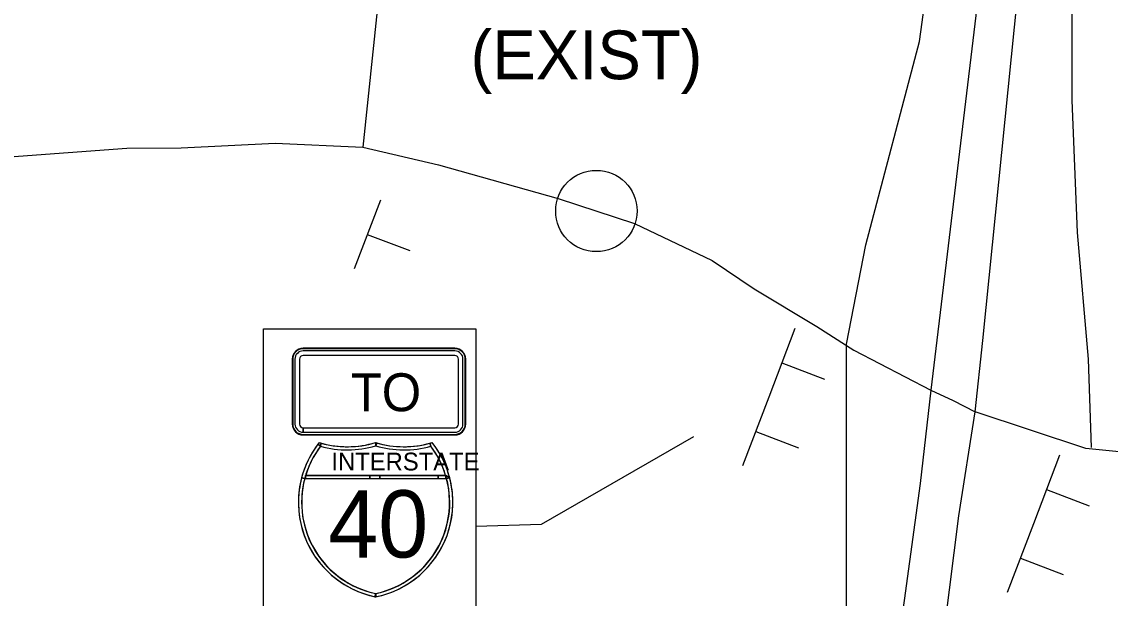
# Model space of a CAD drawing. Extents: x 886234 to 968767, y 455416 to 684046.
# Drawn here: x 913971 to 916482, y 502816 to 504147 of the extents above; entities that cross this region are included whole.
import ezdxf

# ---------------------------------------------------------------- set-up
doc = ezdxf.new("R2010")
doc.units = 0
for name, color, linetype in [('TC DEV SIGN', 7, 'Continuous'), ('TC DEV SIGN BLACK 239', 7, 'Continuous'), ('TC DEV SIGN BLACK ZERO', 7, 'Continuous'), ('TC DEV SIGN WHITE', 7, 'Continuous'), ('TC LABEL TEXT', 7, 'Continuous')]:
    doc.layers.add(name, color=color, linetype=linetype)

msp = doc.modelspace()

# ---------------------------------------------------------------- linework, layer by layer
at = {"layer": 'TC DEV SIGN'}
for p, q in [((914798.7, 503735.3), (914738.4, 503576.6)), ((914768.5, 503656), (914866.9, 503618.6)), ((915754.9, 503438.8), (915694.6, 503280.1)), ((915724.7, 503359.5), (915823.2, 503322.1)), ((915694.6, 503280.1), (915634.3, 503121.4)), ((915664.5, 503200.7), (915762.9, 503163.4)), ((916365.4, 503146.5), (916305.1, 502987.7)), ((916335.3, 503067.1), (916433.7, 503029.7)), ((916305.1, 502987.7), (916244.8, 502829)), ((916275, 502908.4), (916373.4, 502871))]:
    msp.add_line(p, q, dxfattribs=at)
at = {"layer": 'TC DEV SIGN BLACK 239'}
for p, q in [((914970.4, 503386.8), (914620.4, 503386.8)), ((914970.4, 503376.4), (914620.4, 503376.4)), ((914601.6, 503368.1), (914601.6, 503218.1)), ((914612, 503368.1), (914612, 503218.1)), ((914978.7, 503218.1), (914978.7, 503368.1)), ((914989.2, 503218.1), (914989.2, 503368.1)), ((914620.4, 503199.3), (914620.4, 503209.7)), ((914620.5, 503209.7), (914970.4, 503209.7)), ((914620.5, 503209.7), (914620.5, 503199.3)), ((914620.5, 503199.3), (914970.4, 503199.3))]:
    msp.add_line(p, q, dxfattribs=at)
for centre, major_axis, start_param, end_param in [((914620.4, 503368.1), (18.8, 0), 1.570796, 3.141593), ((914620.4, 503368.1), (8.33, 0), 1.570796, 3.141593), ((914970.4, 503368.1), (18.8, 0), 0, 1.570796), ((914970.4, 503368.1), (8.33, 0), 0, 1.570796), ((914620.4, 503218.1), (18.8, 0), 3.141593, 4.712389), ((914620.4, 503218.1), (8.33, 0), 3.141593, 4.712389), ((914970.4, 503218.1), (18.8, 0), 4.712389, 6.283185), ((914970.4, 503218.1), (8.33, 0), 4.712389, 6.283185)]:
    msp.add_ellipse(centre, major_axis=major_axis, ratio=0.999865, start_param=start_param, end_param=end_param, dxfattribs=at)
at = {"layer": 'TC DEV SIGN BLACK ZERO'}
for p, q in [((914970.4, 503393.1), (914620.4, 503393.1)), ((914620.4, 503392), (914620.4, 503392)), ((914970.4, 503392), (914620.4, 503392)), ((914970.4, 503392), (914970.4, 503392)), ((914595.4, 503368.1), (914595.4, 503218.1)), ((914596.4, 503368.1), (914596.4, 503218.1)), ((914596.4, 503368.1), (914596.4, 503368.1)), ((914994.4, 503368.1), (914994.4, 503368.1)), ((914994.4, 503218.1), (914994.4, 503368.1)), ((914995.4, 503218.1), (914995.4, 503368.1)), ((914596.4, 503218.1), (914596.4, 503218.1)), ((914994.4, 503218.1), (914994.4, 503218.1)), ((914620.4, 503193.1), (914620.4, 503194.1)), ((914620.4, 503194.1), (914620.4, 503194.1)), ((914620.4, 503194.1), (914970.4, 503194.1)), ((914620.4, 503194.1), (914620.4, 503193.1)), ((914620.4, 503193.1), (914970.4, 503193.1)), ((914660.4, 503167), (914662.4, 503174.2)), ((914788, 503167.8), (914787.8, 503175.6)), ((914788, 503168.4), (914787.8, 503175.6)), ((914913.1, 503174.2), (914915.1, 503167)), ((914970.4, 503194.1), (914970.4, 503194.1)), ((914626.2, 503099.6), (914949.3, 503099.6)), ((914774.2, 503099.6), (914626.2, 503099.6)), ((914797.6, 503099.6), (914774.2, 503099.6)), ((914931.9, 503099.6), (914797.6, 503099.6)), ((914949.3, 503099.6), (914931.9, 503099.6)), ((914958.6, 503094.1), (914949.3, 503099.6)), ((914624.1, 503092.2), (914951.4, 503092.2)), ((914624.1, 503092.2), (914626.2, 503092.2)), ((914626.2, 503092.2), (914774.2, 503092.2)), ((914774.2, 503092.2), (914797.6, 503092.2)), ((914797.6, 503092.2), (914931.9, 503092.2)), ((914931.9, 503092.2), (914949.3, 503092.2)), ((914951.3, 503092.7), (914949.3, 503092.2)), ((914949.3, 503092.2), (914951.4, 503092.2)), ((914609.7, 503038.6), (914609.7, 503036.4)), ((914965.9, 503036.3), (914965.9, 503038.6))]:
    msp.add_line(p, q, dxfattribs=at)
for points in [[(914657.7, 503175.6), (914657.6, 503175.6), (914657.6, 503175.6)], [(914662.4, 503174.2), (914660.4, 503167)], [(914788, 503175.5), (914788, 503168.4), (914790.1, 503174.9)], [(914790.1, 503174.9), (914788, 503167.8)], [(914915.1, 503167), (914913.1, 503174.2)], [(914917.9, 503175.6), (914917.9, 503175.6), (914917.9, 503175.6)], [(914654.5, 503171.5), (914660.4, 503167)], [(914660.4, 503167), (914654.5, 503171.5)], [(914787.8, 503167.8), (914788, 503168.4)], [(914626.2, 503099.6), (914626.2, 503092.2)], [(914626.2, 503092.2), (914626.2, 503099.6)], [(914774.2, 503092.2), (914774.2, 503099.6)], [(914774.2, 503099.6), (914774.2, 503092.2)], [(914797.6, 503099.6), (914797.6, 503092.2)], [(914797.6, 503092.2), (914797.6, 503099.6)], [(914931.9, 503092.2), (914931.9, 503099.6)], [(914931.9, 503099.6), (914931.9, 503092.2)], [(914949.3, 503099.6), (914958.6, 503094.1)], [(914949.3, 503092.2), (914949.3, 503099.6)], [(914949.3, 503099.6), (914949.3, 503092.2), (914951.3, 503092.7), (914949.3, 503099.6)], [(914617, 503094.1), (914624.1, 503092.2)], [(914624.1, 503092.2), (914617, 503094.1)], [(914951.4, 503092.2), (914951.3, 503092.7)], [(914958.6, 503094.1), (914951.4, 503092.2)], [(914951.4, 503092.2), (914958.6, 503094.1)], [(914786.2, 502819.6), (914787.8, 502826.9)], [(914787.8, 502826.9), (914787.8, 502819.3)]]:
    msp.add_lwpolyline(points, dxfattribs=at)
for centre, radius, start, end in [((914832.3, 503037.5), 222.7, 141.6693, 258.4631), ((914832.3, 503037.5), 222.7, 141.6709, 142.9968), ((914722.7, 503388.5), 222.7, 253.0062, 286.9901), ((914722.7, 503388.5), 222.7, 253.0099, 254.2907), ((914722.7, 503388.5), 222.7, 254.2907, 286.9893), ((914852.8, 503388.5), 222.7, 253.0099, 286.9938), ((914743.2, 503037.5), 222.7, 281.5369, 38.3307), ((914852.8, 503388.5), 222.7, 253.0588, 253.6206), ((914852.8, 503388.5), 222.7, 253.6206, 285.7093), ((914852.8, 503388.5), 222.7, 285.7093, 286.9901), ((914743.2, 503037.5), 222.7, 14.7231, 38.3291), ((914832.3, 503037.5), 222.7, 142.9968, 165.2769), ((914832.3, 503037.5), 215.2, 142.9968, 258.0595), ((914832.3, 503037.5), 215.2, 142.9968, 165.2769), ((914722.7, 503388.5), 230.1, 254.2907, 286.4259), ((914722.7, 503388.5), 230.1, 254.2907, 286.4259), ((914852.8, 503388.5), 230.1, 253.5741, 285.7093), ((914743.2, 503037.5), 215.2, 281.9405, 37.0032), ((914852.9, 503388.2), 229.7, 253.5731, 285.7093), ((914743.2, 503037.5), 215.2, 16.7759, 37.0032), ((914832.3, 503037.5), 215.2, 163.2241, 165.2769), ((914743.2, 503037.5), 215.2, 14.7231, 16.7759), ((914832.3, 503037.5), 222.7, 165.2769, 179.7177), ((914831.3, 503036.8), 214.4, 165.0438, 258.3001), ((914744.3, 503036.8), 214.4, 281.7196, 14.964), ((914743.2, 503037.5), 222.7, 0.2997, 14.7231), ((914832.3, 503037.5), 222.7, 180.2823, 258.0591), ((914743.2, 503037.5), 222.7, 281.537, 359.7003), ((914743.2, 503037.5), 215.2, 281.9405, 281.9604)]:
    msp.add_arc(centre, radius, start, end, dxfattribs=at)
for centre, major_axis, start_param, end_param in [((914620.4, 503368.1), (25, 0), 1.570796, 3.141593), ((914620.4, 503368.1), (24, 0), 1.570796, 3.141593), ((914970.4, 503368.1), (25, 0), 0, 1.570796), ((914970.4, 503368.1), (24, 0), 0, 1.570796), ((914620.4, 503218.1), (25, 0), 3.141593, 4.712389), ((914620.4, 503218.1), (24, 0), 3.141593, 4.712389), ((914970.4, 503218.1), (25, 0), 4.712389, 6.283185), ((914970.4, 503218.1), (24, 0), 4.712389, 6.283185)]:
    msp.add_ellipse(centre, major_axis=major_axis, ratio=0.999865, start_param=start_param, end_param=end_param, dxfattribs=at)
at = {"layer": 'TC DEV SIGN WHITE'}
for p, q in [((914970.4, 503393.1), (914620.4, 503393.1)), ((914595.4, 503368.1), (914595.4, 503218.1)), ((914995.4, 503218.1), (914995.4, 503368.1)), ((914620.4, 503193.1), (914970.4, 503193.1)), ((914787.8, 502819.3), (914787.8, 502826.9))]:
    msp.add_line(p, q, dxfattribs=at)
msp.add_lwpolyline([(914787.8, 502826.9), (914786.2, 502819.6), (914787.8, 502819.3)], dxfattribs=at)
for centre, start, end in [((914832.3, 503037.5), 258.458, 258.463), ((914743.2, 503037.5), 281.5369590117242, 281.53700435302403)]:
    msp.add_arc(centre, 222.7, start, end, dxfattribs=at)
for centre, start_param, end_param in [((914620.4, 503368.1), 1.570796, 3.141593), ((914970.4, 503368.1), 0, 1.570796), ((914620.4, 503218.1), 3.141593, 4.712389), ((914970.4, 503218.1), 4.712389, 6.283185)]:
    msp.add_ellipse(centre, major_axis=(25, 0), ratio=0.999865, start_param=start_param, end_param=end_param, dxfattribs=at)
at = {"layer": 'TC LABEL TEXT'}
for points in [[(915874.2, 503402.2), (915918.4, 503632.2), (916042.2, 504101), (916113.5, 504621.9), (916224.9, 505583.1)], [(916224.9, 505583.1), (916240.7, 505073.9), (916174.8, 504180.6), (916068.7, 503296)], [(916170.7, 503246.7), (916188.4, 503410.7), (916298, 504500.9), (916329.8, 505271.2)], [(916329.8, 505271.2), (916387.1, 504793.7), (916393.4, 504329), (916393.4, 503966.1), (916406.2, 503660.5), (916431.6, 503367.7), (916438, 503163.9)], [(915075.4, 504821.5), (914859.1, 504819), (914758.5, 503857)], [(911185.8, 503694.9), (911359, 503839.4), (911503.5, 503907.3), (911735, 504004.9), (911903.4, 504050), (912065.3, 504090.1), (912149.9, 504095.3), (912277, 504097), (912661.8, 504042.1), (913295.7, 503879.5), (913546.6, 503834.6), (913807.1, 503825), (914213.8, 503855.3), (914339.3, 503855.7), (914555.9, 503866.2), (914758.5, 503857), (914932.9, 503816.5), (915209, 503738.7), (915384.6, 503681.3), (915563.9, 503595.9), (915661, 503530.1), (915805.5, 503443), (915890.8, 503389), (916068.7, 503296)], [(915874.2, 501760.6), (915874.2, 503013), (915874.2, 503181), (915874.2, 503402.2)], [(916068.7, 503296), (916043.5, 503081.2), (915918.4, 502163.8), (915847.6, 501518.3), (915794.8, 501201.3), (915771.4, 501007.6), (915665.8, 500455.8), (915564.8, 500147), (915378.3, 499663.4)], [(916068.7, 503296), (916119.8, 503272.2), (916170.7, 503246.7)], [(914514.9, 497965.9), (914613.1, 498228.3), (914701.8, 498403.8), (914803.7, 498581.2), (914913.1, 498751), (915202.3, 499146.9), (915425.3, 499534.3), (915630.6, 499998), (915753.8, 500367.8), (915818.3, 500649.5), (915888.7, 501066.3), (916133.3, 503006.5), (916170.7, 503246.7)], [(918298, 503148.1), (917629.7, 503227.3), (917494.5, 503244.8), (917115.1, 503188), (916836, 503153.1), (916556.9, 503148.8), (916426.1, 503161.8), (916170.7, 503246.7)], [(915019.1, 502982.1), (915170, 502986.7), (915521.4, 503189.5)]]:
    msp.add_lwpolyline(points, dxfattribs=at)
msp.add_lwpolyline([(914529.3, 503437.6), (915019.1, 503437.6), (915019.1, 502526.6), (914529.3, 502526.6)], close=True, dxfattribs=at)
msp.add_circle((915296.8, 503710), 93.8, dxfattribs=at)
msp.add_circle((915296.8, 503710), 93.8, dxfattribs=at)

# ---------------------------------------------------------------- texts
at = {"layer": 'TC DEV SIGN BLACK 239'}
msp.add_text('TO', height=87.5, rotation=360, dxfattribs=at).set_placement((914730.3, 503247.8))
at = {"layer": 'TC DEV SIGN BLACK ZERO'}
for s, height, p in [('INTERSTATE', 41.06, (914685.7, 503111.1)), ('40', 155.13, (914678.3, 502910))]:
    msp.add_text(s, height=height, rotation=360, dxfattribs=at).set_placement(p)
at = {"layer": 'TC LABEL TEXT'}
msp.add_text('(EXIST)', height=112.5, dxfattribs=at).set_placement((915006.6, 504014.2))

doc.saveas('drawing.dxf')
